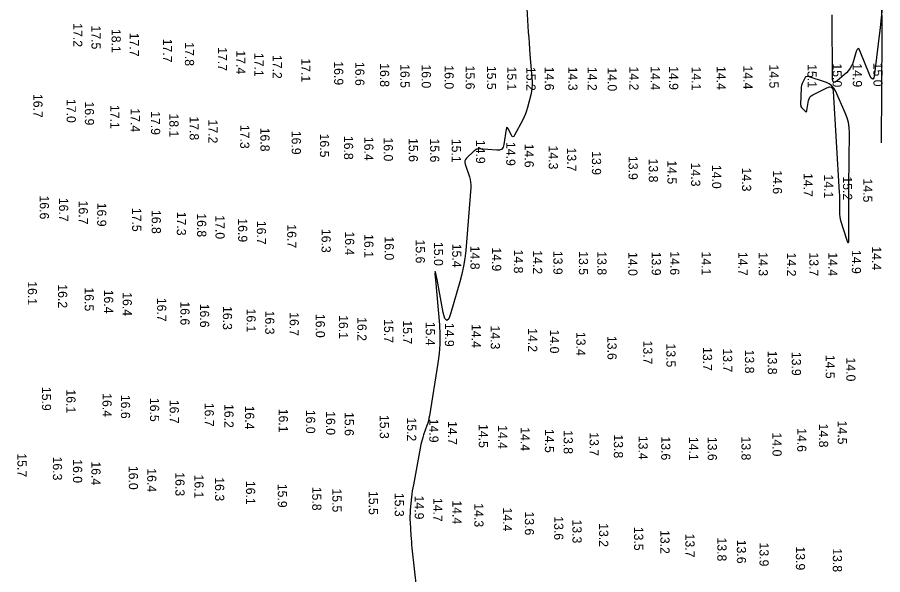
# Model space of a CAD drawing. Extents: x 988130 to 1132882, y 654656 to 841453.
# Drawn here: x 1109997.2 to 1110469.1, y 672506.7 to 672810.8 of the extents above; entities that cross this region are included whole.
import ezdxf

# ---------------------------------------------------------------- set-up
doc = ezdxf.new("R2010")
doc.units = 0
doc.layers.add('V-TOPO-MAJR', color=7, linetype='Continuous')
doc.layers.add('V-TOPO-SOUN', color=7, linetype='Continuous')

msp = doc.modelspace()

# ---------------------------------------------------------------- linework, layer by layer
at = {"layer": 'V-TOPO-MAJR'}
for points in [[(1110274.24, 672828.97), (1110275.85, 672802.72), (1110276.04, 672799.65), (1110276.25, 672796.59), (1110276.47, 672793.52), (1110276.7, 672790.45), (1110277.86, 672775.67), (1110277.92, 672773.87), (1110277.84, 672772.09), (1110277.6, 672770.32), (1110277.22, 672768.56), (1110275.38, 672761.56), (1110274.88, 672759.83), (1110274.28, 672758.13), (1110273.58, 672756.48), (1110272.79, 672754.86), (1110268.37, 672746.43), (1110267.92, 672745.79), (1110267.48, 672745.59), (1110267.05, 672745.81), (1110266.62, 672746.46), (1110264.92, 672749.92), (1110264.53, 672750.55), (1110264.21, 672750.74), (1110263.96, 672750.46), (1110263.78, 672749.74), (1110262.56, 672741.42), (1110262.13, 672739.94), (1110261.33, 672738.92), (1110260.16, 672738.36), (1110258.62, 672738.25), (1110248.81, 672738.95), (1110248.56, 672738.95), (1110248.32, 672738.92), (1110248.08, 672738.85), (1110247.85, 672738.75), (1110246.95, 672738.28), (1110246.73, 672738.15), (1110246.52, 672738.01), (1110246.32, 672737.86), (1110246.13, 672737.69), (1110242.14, 672733.91), (1110241.55, 672733.19), (1110241.22, 672732.41), (1110241.15, 672731.56), (1110241.34, 672730.64), (1110243.7, 672723.82), (1110244.13, 672722.36), (1110244.39, 672720.88), (1110244.5, 672719.38), (1110244.46, 672717.86), (1110241.69, 672683.63), (1110241.23, 672679.26), (1110240.55, 672674.93), (1110239.64, 672670.64), (1110238.52, 672666.39), (1110233.61, 672649.47), (1110232.43, 672646.31), (1110231.35, 672645.29), (1110230.37, 672646.4), (1110229.49, 672649.66), (1110226.06, 672667.64), (1110225.37, 672670.96), (1110224.99, 672672.05), (1110224.92, 672670.9), (1110225.17, 672667.52), (1110227.33, 672643.05), (1110227.63, 672637.78), (1110227.61, 672632.52), (1110227.25, 672627.27), (1110226.57, 672622.04), (1110221.91, 672593.37), (1110221.66, 672592.02), (1110221.35, 672590.69), (1110220.98, 672589.38), (1110220.55, 672588.08), (1110218.72, 672582.9), (1110218.29, 672581.6), (1110217.91, 672580.29), (1110217.58, 672578.96), (1110217.3, 672577.62), (1110213.15, 672555.78), (1110212.85, 672554.07), (1110212.58, 672552.35), (1110212.36, 672550.63), (1110212.17, 672548.9), (1110211.51, 672541.98), (1110211.37, 672540.25), (1110211.31, 672538.52), (1110211.31, 672536.79), (1110211.38, 672535.06), (1110211.81, 672528.12), (1110211.92, 672526.39), (1110212.06, 672524.66), (1110212.21, 672522.93), (1110212.39, 672521.2), (1110216.07, 672487.24)], [(1110468.75, 672815.62), (1110468.21, 672810.46), (1110467.62, 672805.3), (1110464.65, 672779.95), (1110464.24, 672777.83), (1110463.64, 672777.06), (1110462.86, 672777.65), (1110461.9, 672779.58), (1110456.82, 672792.21), (1110456.23, 672793.35), (1110455.67, 672793.71), (1110455.14, 672793.3), (1110454.64, 672792.12), (1110452.71, 672785.84), (1110452.14, 672784.33), (1110451.38, 672782.95), (1110450.42, 672781.68), (1110449.28, 672780.54), (1110444.28, 672776.15), (1110443.19, 672775.4), (1110442.41, 672775.33), (1110441.93, 672775.96), (1110441.77, 672777.27), (1110441.51, 672812.19)], [(1110468.41, 672742.2), (1110468.74, 672800.52), (1110468.71, 672808.06), (1110468.53, 672815.6)]]:
    msp.add_lwpolyline(points, dxfattribs=at)
msp.add_lwpolyline([(1110426.95, 672778.2), (1110426.85, 672778.08), (1110426.76, 672777.95), (1110425.19, 672774.71), (1110424.93, 672774.11), (1110424.75, 672773.5), (1110424.63, 672772.87), (1110424.58, 672772.22), (1110424.33, 672763.13), (1110424.37, 672762.57), (1110424.51, 672762.06), (1110424.76, 672761.59), (1110425.11, 672761.16), (1110426.73, 672759.52), (1110427.1, 672759.24), (1110427.39, 672759.19), (1110427.6, 672759.4), (1110427.73, 672759.84), (1110428.63, 672765.33), (1110428.91, 672766.36), (1110429.4, 672767.23), (1110430.09, 672767.96), (1110430.99, 672768.54), (1110438.59, 672772.35), (1110440, 672772.83), (1110441.04, 672772.66), (1110441.71, 672771.85), (1110442.01, 672770.39), (1110445.39, 672715.13), (1110445.46, 672713.82), (1110445.5, 672712.5), (1110445.52, 672711.18), (1110445.52, 672709.86), (1110445.45, 672704.59), (1110445.49, 672703.28), (1110445.63, 672701.99), (1110445.87, 672700.71), (1110446.22, 672699.45), (1110449.33, 672689.65), (1110449.9, 672688.13), (1110450.31, 672687.65), (1110450.55, 672688.23), (1110450.63, 672689.86), (1110450.59, 672705.38), (1110450.59, 672708.68), (1110450.59, 672711.98), (1110450.61, 672715.29), (1110450.64, 672718.59), (1110450.94, 672747.82), (1110450.82, 672750.6), (1110450.4, 672753.32), (1110449.7, 672755.97), (1110448.69, 672758.57), (1110443.26, 672770.68), (1110442.41, 672772.19), (1110441.31, 672773.43), (1110439.97, 672774.42), (1110438.39, 672775.13), (1110428.51, 672778.55), (1110428.35, 672778.59), (1110428.19, 672778.6), (1110428.03, 672778.59), (1110427.87, 672778.55), (1110427.23, 672778.35), (1110427.08, 672778.29)], close=True, dxfattribs=at)

# ---------------------------------------------------------------- texts
at = {"layer": 'V-TOPO-SOUN'}
for s, p in [('17.2 ', (1110027.67, 672807.55)), ('17.5 ', (1110037.66, 672806.3)), ('18.1 ', (1110048.61, 672804.44)), ('17.7 ', (1110058.48, 672802.37)), ('17.7 ', (1110076.64, 672799.1)), ('17.8 ', (1110088.59, 672797.2)), ('17.7 ', (1110106.63, 672794.46)), ('17.4 ', (1110116.59, 672792.74)), ('17.1 ', (1110126.51, 672791.36)), ('17.2 ', (1110136.48, 672790.25)), ('17.1 ', (1110152.04, 672788.39)), ('16.9 ', (1110169.96, 672786.77)), ('16.6 ', (1110181.48, 672786.44)), ('16.8 ', (1110195, 672785.75)), ('16.5 ', (1110206.08, 672785.23)), ('16.0 ', (1110217.71, 672785.07)), ('16.0 ', (1110230.17, 672784.58)), ('15.6 ', (1110241.67, 672784.41)), ('15.5 ', (1110253.31, 672784.31)), ('15.1 ', (1110264.32, 672783.88)), ('15.2 ', (1110274.79, 672783.69)), ('14.6 ', (1110284.83, 672783.82)), ('14.3 ', (1110297.63, 672783.82)), ('14.2 ', (1110308.21, 672783.73)), ('14.0 ', (1110319.1, 672783.46)), ('14.2 ', (1110330.96, 672783.9)), ('14.4 ', (1110342.59, 672784.09)), ('14.9 ', (1110352.64, 672784.16)), ('14.1 ', (1110364.97, 672783.89)), ('14.4 ', (1110378.5, 672784.2)), ('14.4 ', (1110393.12, 672784.46)), ('14.5 ', (1110407.28, 672785.05)), ('15.1 ', (1110428.08, 672785.23)), ('15.0 ', (1110441.79, 672785.63)), ('14.9 ', (1110452.78, 672785.67)), ('15.0 ', (1110464, 672786.03)), ('16.7 ', (1110005.97, 672768.97)), ('17.0 ', (1110024.12, 672766.23)), ('16.9 ', (1110034.05, 672764.83)), ('17.1 ', (1110047.9, 672762.95)), ('17.4 ', (1110059.02, 672761.14)), ('17.9 ', (1110070.1, 672759.6)), ('18.1 ', (1110080.13, 672758.31)), ('17.8 ', (1110091.18, 672756.71)), ('17.2 ', (1110101.42, 672754.99)), ('17.3 ', (1110118.75, 672752.11)), ('16.8 ', (1110129.77, 672750.55)), ('16.9 ', (1110146.83, 672748.87)), ('16.5 ', (1110162.22, 672747.32)), ('16.8 ', (1110175.33, 672746.09)), ('16.4 ', (1110186.4, 672745.55)), ('16.0 ', (1110197.02, 672745.21)), ('15.6 ', (1110210.66, 672744.9)), ('15.6 ', (1110222.32, 672744.66)), ('15.1 ', (1110234.08, 672744.48)), ('14.9 ', (1110247.3, 672743.93)), ('14.9 ', (1110263.81, 672742.75)), ('14.6 ', (1110273.82, 672741.81)), ('14.3 ', (1110286.99, 672740.8)), ('13.7 ', (1110296.98, 672739.69)), ('13.9 ', (1110310.53, 672737.75)), ('13.9 ', (1110330.51, 672735.12)), ('13.8 ', (1110341.54, 672733.7)), ('14.5 ', (1110351.7, 672732.73)), ('14.3 ', (1110364.61, 672731.48)), ('14.0 ', (1110376.06, 672730.28)), ('14.3 ', (1110392.37, 672728.78)), ('14.6 ', (1110409.19, 672727.31)), ('14.7 ', (1110425.93, 672725.81)), ('14.1 ', (1110437.14, 672724.98)), ('15.2 ', (1110447.42, 672723.99)), ('14.5 ', (1110458.45, 672722.81)), ('16.6 ', (1110009.48, 672713.56)), ('16.7 ', (1110019.97, 672712.3)), ('16.7 ', (1110030.71, 672710.74)), ('16.9 ', (1110040.76, 672709.61)), ('17.5 ', (1110059.83, 672706.81)), ('16.8 ', (1110070.5, 672705.66)), ('17.3 ', (1110084.2, 672704.7)), ('16.8 ', (1110095.25, 672703.85)), ('17.0 ', (1110105.27, 672702.77)), ('16.9 ', (1110117.63, 672701.1)), ('16.7 ', (1110127.84, 672699.73)), ('16.7 ', (1110144.37, 672697.83)), ('16.3 ', (1110163.11, 672695.33)), ('16.4 ', (1110175.95, 672693.93)), ('16.1 ', (1110186.4, 672692.5)), ('16.0 ', (1110197.52, 672691.23)), ('15.6 ', (1110214.45, 672689.53)), ('15.0 ', (1110224.37, 672688.19)), ('15.4 ', (1110234.33, 672687.23)), ('14.8 ', (1110244.31, 672686.16)), ('14.9 ', (1110256.07, 672685.23)), ('14.8 ', (1110267.97, 672684.05)), ('14.2 ', (1110278.42, 672683.65)), ('13.9 ', (1110289.5, 672683.37)), ('13.5 ', (1110303.42, 672683.16)), ('13.8 ', (1110313.48, 672683.12)), ('14.0 ', (1110330.35, 672682.72)), ('13.9 ', (1110343.12, 672682.9)), ('14.6 ', (1110353.22, 672683.12)), ('14.1 ', (1110370.39, 672683.01)), ('14.7 ', (1110390.38, 672682.77)), ('14.3 ', (1110401.42, 672682.6)), ('14.4 ', (1110439.41, 672682.54)), ('14.9 ', (1110452.25, 672683.84)), ('14.4 ', (1110463.26, 672685.8)), ('14.2 ', (1110416.83, 672682.41)), ('13.7 ', (1110429.05, 672682.49)), ('16.1 ', (1110002.95, 672666.76)), ('16.2 ', (1110019.44, 672665.11)), ('16.5 ', (1110033.92, 672663.42)), ('16.4 ', (1110044.51, 672662.16)), ('16.4 ', (1110054.67, 672660.79)), ('16.7 ', (1110073.46, 672657.75)), ('16.6 ', (1110086.16, 672655.78)), ('16.6 ', (1110096.83, 672654.51)), ('16.3 ', (1110109.31, 672653.25)), ('16.1 ', (1110122.22, 672651.86)), ('16.3 ', (1110132.39, 672650.72)), ('16.7 ', (1110145.71, 672649.88)), ('16.0 ', (1110159.95, 672648.97)), ('16.1 ', (1110172.53, 672648.3)), ('16.2 ', (1110182.67, 672647.2)), ('15.7 ', (1110197.2, 672646.1)), ('15.7 ', (1110207.47, 672645.4)), ('15.4 ', (1110219.93, 672644.66)), ('14.9 ', (1110230.35, 672644.04)), ('14.4 ', (1110244.96, 672643.41)), ('14.3 ', (1110255.34, 672642.62)), ('14.2 ', (1110275.73, 672641.15)), ('14.0 ', (1110287.65, 672640.4)), ('13.4 ', (1110302.02, 672639.13)), ('13.6 ', (1110319.01, 672636.92)), ('13.7 ', (1110338.5, 672634.39)), ('13.5 ', (1110351.12, 672632.82)), ('13.7 ', (1110371.05, 672630.85)), ('13.7 ', (1110382.02, 672630.11)), ('13.8 ', (1110393.97, 672629.44)), ('13.8 ', (1110406.44, 672628.87)), ('13.9 ', (1110419.53, 672628.23)), ('14.5 ', (1110437.96, 672626.62)), ('14.0 ', (1110449.24, 672625.15)), ('15.9 ', (1110010.62, 672609.13)), ('16.1 ', (1110023.98, 672607.75)), ('16.4 ', (1110043.67, 672605.69)), ('16.6 ', (1110053.7, 672604.8)), ('16.5 ', (1110069.56, 672603.13)), ('16.7 ', (1110080.31, 672602.08)), ('16.7 ', (1110099.37, 672600.47)), ('16.2 ', (1110110.13, 672599.79)), ('16.4 ', (1110121.41, 672598.88)), ('16.1 ', (1110139.78, 672597.22)), ('16.0 ', (1110154.66, 672596.64)), ('16.0 ', (1110165.59, 672595.86)), ('15.6 ', (1110175.72, 672595.39)), ('15.3 ', (1110194.87, 672593.84)), ('15.2 ', (1110209.73, 672592.46)), ('14.9 ', (1110221.85, 672591.75)), ('14.7 ', (1110231.97, 672590.5)), ('14.5 ', (1110248.84, 672588.87)), ('14.4 ', (1110259.39, 672588.25)), ('14.8 ', (1110434.32, 672589.08)), ('14.5 ', (1110444.57, 672590.74)), ('14.4 ', (1110271.64, 672587.13)), ('14.5 ', (1110284.87, 672586.17)), ('13.8 ', (1110295.09, 672585.5)), ('13.7 ', (1110309.26, 672584.38)), ('14.0 ', (1110408.98, 672584.22)), ('14.6 ', (1110422.46, 672586.64)), ('13.8 ', (1110322.48, 672583.21)), ('13.4 ', (1110335.95, 672582.44)), ('13.6 ', (1110348.29, 672582.11)), ('14.1 ', (1110363.53, 672581.87)), ('13.6 ', (1110373.69, 672581.89)), ('13.8 ', (1110392.08, 672582.05)), ('15.7 ', (1109997.28, 672572.89)), ('16.3 ', (1110016.62, 672571.11)), ('16.0 ', (1110027.59, 672569.66)), ('16.4 ', (1110037.62, 672568.48)), ('16.0 ', (1110058.02, 672566.05)), ('16.4 ', (1110068.04, 672564.7)), ('16.3 ', (1110083.41, 672562.55)), ('16.1 ', (1110093.82, 672561.29)), ('16.3 ', (1110105.03, 672559.8)), ('16.1 ', (1110121.93, 672557.85)), ('15.9 ', (1110139.26, 672556.26)), ('15.8 ', (1110158.01, 672554.64)), ('15.5 ', (1110169.01, 672553.73)), ('15.5 ', (1110188.85, 672552.33)), ('15.3 ', (1110203.02, 672551.32)), ('14.9 ', (1110213.89, 672549.82)), ('14.7 ', (1110224.03, 672548.56)), ('14.4 ', (1110234.47, 672547.19)), ('14.3 ', (1110246.4, 672545.61)), ('14.4 ', (1110261.97, 672543.31)), ('13.6 ', (1110273.96, 672541.16)), ('13.6 ', (1110289.95, 672538.54)), ('13.3 ', (1110299.93, 672536.79)), ('13.2 ', (1110314.45, 672534.77)), ('13.5 ', (1110333.52, 672532.81)), ('13.2 ', (1110347.86, 672531.02)), ('13.7 ', (1110361.49, 672529.07)), ('13.8 ', (1110378.91, 672526.99)), ('13.6 ', (1110389.56, 672525.73)), ('13.9 ', (1110401.91, 672524.2)), ('13.9 ', (1110421.74, 672522.09)), ('13.8 ', (1110441.89, 672521.09))]:
    msp.add_text(s, height=5, rotation=270, dxfattribs=at).set_placement(p)

doc.saveas('drawing.dxf')
